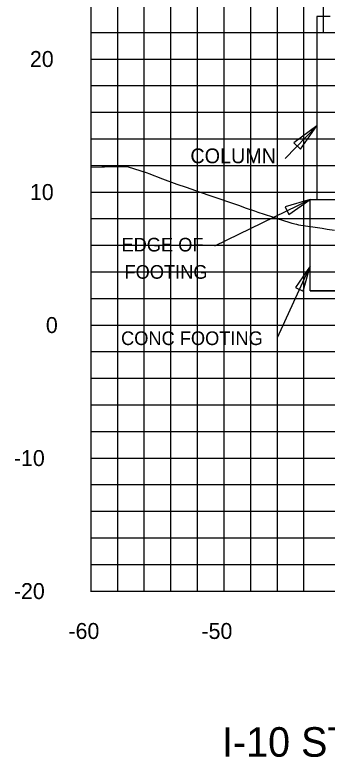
# Model space of a CAD drawing. Extents: x 2193008 to 2198143, y 1236112 to 1237864.
# Drawn here: x 2195322.9 to 2195346.4, y 1237245.6 to 1237301.4 of the extents above; entities that cross this region are included whole.
import ezdxf

# ---------------------------------------------------------------- set-up
doc = ezdxf.new("R2010")
doc.units = 0
for name, color, linetype in [('10', 7, 'Continuous'), ('3', 7, 'Continuous'), ('31', 7, 'Continuous'), ('60', 7, 'Continuous'), ('GSDIMS', 7, 'Continuous'), ('Level 55', 7, 'Continuous'), ('Level 62', 7, 'Continuous'), ('M-ROADS', 7, 'Continuous'), ('V7Level1', 7, 'Continuous')]:
    doc.layers.add(name, color=color, linetype=linetype)

msp = doc.modelspace()

# ---------------------------------------------------------------- linework, layer by layer
msp.add_line((2195346.092, 1237300.108), (2195346.092, 1237307.648))
at = {"layer": '3'}
for p, q in [((2195345.592, 1237301.295), (2195345.592, 1237287.538)), ((2195343.223, 1237290.633), (2195345.592, 1237293.076)), ((2195337.929, 1237284.06), (2195345.092, 1237287.538)), ((2195345.092, 1237287.538), (2195347.092, 1237287.538)), ((2195345.092, 1237280.686), (2195345.092, 1237287.538)), ((2195342.642, 1237277.175), (2195345.092, 1237282.531)), ((2195345.092, 1237280.686), (2195347.092, 1237280.686))]:
    msp.add_line(p, q, dxfattribs=at)
at = {"layer": '60'}
for p, q in [((2195328.632, 1237258.106), (2195328.632, 1237318.106)), ((2195328.632, 1237258.046), (2195328.632, 1237258.106)), ((2195328.632, 1237258.106), (2195448.632, 1237258.106)), ((2195338.632, 1237258.046), (2195338.632, 1237258.106))]:
    msp.add_line(p, q, dxfattribs=at)
at = {"layer": 'GSDIMS'}
msp.add_line((2195346.592, 1237301.295), (2195345.592, 1237301.295), dxfattribs=at)
for points in [[(2195345.592, 1237293.076), (2195343.869, 1237291.804), (2195344.384, 1237291.326)], [(2195345.092, 1237287.538), (2195343.223, 1237286.987), (2195343.503, 1237286.41)], [(2195345.092, 1237282.531), (2195344.001, 1237280.916), (2195344.584, 1237280.65)]]:
    msp.add_lwpolyline(points, close=True, dxfattribs=at)
at = {"layer": 'Level 62'}
for p, q in [((2195328.632, 1237258.106), (2195328.632, 1237318.106)), ((2195330.632, 1237258.106), (2195330.632, 1237318.106)), ((2195332.632, 1237258.106), (2195332.632, 1237318.106)), ((2195334.632, 1237258.106), (2195334.632, 1237318.106)), ((2195336.632, 1237258.106), (2195336.632, 1237318.106)), ((2195338.632, 1237258.106), (2195338.632, 1237318.106)), ((2195340.632, 1237258.106), (2195340.632, 1237318.106)), ((2195342.632, 1237258.106), (2195342.632, 1237318.106)), ((2195344.632, 1237258.106), (2195344.632, 1237318.106)), ((2195328.632, 1237300.106), (2195448.632, 1237300.106)), ((2195328.632, 1237298.106), (2195448.632, 1237298.106)), ((2195328.632, 1237296.106), (2195448.632, 1237296.106)), ((2195328.632, 1237294.106), (2195448.632, 1237294.106)), ((2195328.632, 1237292.106), (2195448.632, 1237292.106)), ((2195328.632, 1237290.106), (2195448.632, 1237290.106)), ((2195328.632, 1237288.106), (2195448.632, 1237288.106)), ((2195328.632, 1237286.106), (2195448.632, 1237286.106)), ((2195328.632, 1237284.106), (2195448.632, 1237284.106)), ((2195328.632, 1237282.106), (2195448.632, 1237282.106)), ((2195328.632, 1237280.106), (2195448.632, 1237280.106)), ((2195328.632, 1237278.106), (2195448.632, 1237278.106)), ((2195328.632, 1237276.106), (2195448.632, 1237276.106)), ((2195328.632, 1237274.106), (2195448.632, 1237274.106)), ((2195328.632, 1237272.106), (2195448.632, 1237272.106)), ((2195328.632, 1237270.106), (2195448.632, 1237270.106)), ((2195328.632, 1237268.106), (2195448.632, 1237268.106)), ((2195328.632, 1237266.106), (2195448.632, 1237266.106)), ((2195328.632, 1237264.106), (2195448.632, 1237264.106)), ((2195328.632, 1237262.106), (2195448.632, 1237262.106)), ((2195328.632, 1237260.106), (2195448.632, 1237260.106)), ((2195328.632, 1237258.106), (2195448.632, 1237258.106))]:
    msp.add_line(p, q, dxfattribs=at)
at = {"layer": 'M-ROADS'}
msp.add_lwpolyline([(2195328.632, 1237289.968), (2195329.439, 1237289.997), (2195329.639, 1237290), (2195331.338, 1237290.031), (2195332.852, 1237289.548), (2195332.967, 1237289.508), (2195334.005, 1237289.106), (2195335.08, 1237288.708), (2195335.781, 1237288.464), (2195336.825, 1237288.094), (2195337.638, 1237287.812), (2195339.7, 1237287.106), (2195340.291, 1237286.903), (2195340.91, 1237286.693), (2195341.171, 1237286.604), (2195341.635, 1237286.446), (2195342.259, 1237286.232), (2195342.629, 1237286.106), (2195343.499, 1237285.835), (2195343.713, 1237285.772), (2195344.065, 1237285.679), (2195344.227, 1237285.639), (2195345.995, 1237285.392), (2195346.372, 1237285.319), (2195346.923, 1237285.247)], dxfattribs=at)
at = {"layer": 'V7Level1'}
msp.add_lwpolyline([(2195347.092, 1237280.686), (2195345.092, 1237280.686), (2195345.092, 1237287.538), (2195347.092, 1237287.538)], close=True, dxfattribs=at)

# ---------------------------------------------------------------- texts
at = {"layer": '10'}
for s, p in [('-60', (2195326.929, 1237254.506)), ('-50', (2195336.929, 1237254.506))]:
    msp.add_text(s, height=1.2, dxfattribs=at).set_placement(p)
at = {"layer": '31'}
for s, p in [('20', (2195324.031, 1237297.506)), ('10', (2195324.031, 1237287.506)), ('0', (2195325.231, 1237277.506)), ('-10', (2195322.826, 1237267.506)), ('-20', (2195322.826, 1237257.506))]:
    msp.add_text(s, height=1.2, dxfattribs=at).set_placement(p)
at = {"layer": 'Level 55'}
for s, height, p in [('COLUMN', 1.1105, (2195336.096, 1237290.27)), ('EDGE OF', 1.0246, (2195330.916, 1237283.637)), ('FOOTING', 1.0246, (2195331.141, 1237281.587)), ('CONC FOOTING', 1.02464, (2195330.883, 1237276.602))]:
    msp.add_text(s, height=height, rotation=360, dxfattribs=at).set_placement(p)
msp.add_text('I-10 STA. 161+00 WBR & EBR', height=2.22092, dxfattribs=at).set_placement((2195338.472, 1237245.652))

doc.saveas('drawing.dxf')
